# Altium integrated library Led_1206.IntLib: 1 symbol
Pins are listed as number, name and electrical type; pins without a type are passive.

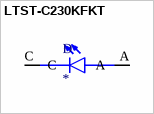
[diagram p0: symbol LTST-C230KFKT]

## LTST-C230KFKT
designator D
Orange 605nm LED Indication - Discrete 2V 1206 (3216 Metric); MF: Lite-On Inc.; MP: LTST-C230KFKT
footprint LEDC3216X110
pins: A, C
